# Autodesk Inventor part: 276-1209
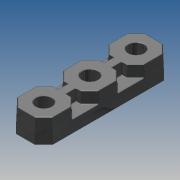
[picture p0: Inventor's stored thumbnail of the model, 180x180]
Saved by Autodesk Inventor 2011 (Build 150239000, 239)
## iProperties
Company: Autodesk Inc.
Created: 2010-06
Part Number: 276-1209
Document SubType Name: Modeling
Designer: Autodesk Inc.
Density: 1 g/cm^3
Catalog Web Link: http://www.vexrobotics.com/276-1209.html
Description: The Bearing Flat mounts directly on a piece of VEX structure and supports a shaft which runs perpendicular and directly through
Vendor: Innovation First, Inc.
Author: Autodesk Inc.
Title: VEX Robotics Kit of Parts
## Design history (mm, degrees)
sketch "Sketch1"
  geometry: L1 (11.392, 8.68)-(5.192, 8.68); L2 (5.192, 1.48)-(11.392, 1.48); L3 (4.802, 6.071)-(4.802, 6.833); L4 (5.192, 8.68)-(5.192, 1.48); L5 (4.63, 6.071)-(4.802, 6.071); L6 (4.802, 4.089)-(4.63, 4.089); L7 (4.802, 3.327)-(4.802, 4.089); L8 (30.483, 0)-(0, 0); L9 (0, 10.16)-(30.483, 10.16); L10 (0.281, 6.833)-(0.281, 6.071); L11 (0.281, 6.071)-(0.453, 6.071); L12 (0.453, 4.089)-(0.281, 4.089); L13 (1.551, 2.819)-(1.551, 2.992); L14 (0.281, 4.089)-(0.281, 3.327); L15 (0.789, 2.819)-(1.551, 2.819); L16 (-2.538, 2.538)-(0, 0); L17 (-2.538, 2.538)-(-2.538, 7.622); L18 (1.551, 7.168)-(1.551, 7.341); L19 (1.551, 7.341)-(0.789, 7.341); L20 (3.532, 2.992)-(3.532, 2.819); L21 (3.532, 7.341)-(3.532, 7.168); L22 (3.532, 2.819)-(4.294, 2.819); L23 (4.294, 7.341)-(3.532, 7.341); L24 (28.932, 2.992)-(28.932, 2.819); L25 (28.932, 2.819)-(29.694, 2.819); L26 (30.202, 4.089)-(30.03, 4.089); L27 (30.202, 3.327)-(30.202, 4.089); L28 (33.022, 2.538)-(30.483, 0); L29 (28.932, 7.341)-(28.932, 7.168); L30 (30.03, 6.071)-(30.202, 6.071); L31 (30.202, 6.071)-(30.202, 6.833); L32 (29.694, 7.341)-(28.932, 7.341); L33 (33.022, 7.622)-(33.022, 2.538); L34 (33.022, 7.622)-(30.483, 10.16); L35 (26.951, 2.819)-(26.951, 2.992); L36 (26.951, 7.168)-(26.951, 7.341); L37 (26.951, 7.341)-(26.189, 7.341); L38 (25.681, 6.833)-(25.681, 6.071); L39 (25.681, 6.071)-(25.853, 6.071); L40 (25.853, 4.089)-(25.681, 4.089); L41 (26.189, 2.819)-(26.951, 2.819); L42 (25.681, 4.089)-(25.681, 3.327); L43 (12.981, 6.833)-(12.981, 6.071); L44 (14.251, 7.341)-(13.489, 7.341); L45 (14.251, 7.168)-(14.251, 7.341); L46 (12.981, 6.071)-(13.153, 6.071); L47 (13.489, 2.819)-(14.251, 2.819); L48 (12.981, 4.089)-(12.981, 3.327); L49 (13.153, 4.089)-(12.981, 4.089); L50 (14.251, 2.819)-(14.251, 2.992); L51 (17.502, 3.327)-(17.502, 4.089); L52 (16.232, 2.819)-(16.994, 2.819); L53 (16.232, 2.992)-(16.232, 2.819); L54 (17.502, 4.089)-(17.33, 4.089); L55 (16.994, 7.341)-(16.232, 7.341); L56 (17.502, 6.071)-(17.502, 6.833); L57 (17.33, 6.071)-(17.502, 6.071); L58 (16.232, 7.341)-(16.232, 7.168); L59 (11.392, 1.48)-(11.392, 8.68); L60 (19.092, 1.48)-(25.292, 1.48); L61 (25.292, 8.68)-(19.092, 8.68); L62 (19.092, 8.68)-(19.092, 1.48); L63 (25.292, 1.48)-(25.292, 8.68); L64 (-2.538, 7.622)-(0, 10.16); C1 r 2.121 at (2.542, 5.08); C2 r 2.121 at (27.942, 5.08); C3 r 2.121 at (15.242, 5.08); A1 r 2.311 centre (2.542, 5.08) between (0.453, 4.089) and (1.551, 2.992); A2 r 2.311 centre (2.542, 5.08) between (1.551, 7.168) and (0.453, 6.071); A3 r 2.311 centre (2.542, 5.08) between (3.532, 2.992) and (4.63, 4.089); A4 r 2.311 centre (2.542, 5.08) between (4.63, 6.071) and (3.532, 7.168); A5 r 2.311 centre (27.942, 5.08) between (28.932, 2.992) and (30.03, 4.089); A6 r 2.311 centre (27.942, 5.08) between (30.03, 6.071) and (28.932, 7.168); A7 r 2.311 centre (27.942, 5.08) between (26.951, 7.168) and (25.853, 6.071); A8 r 2.311 centre (27.942, 5.08) between (25.853, 4.089) and (26.951, 2.992); A9 r 2.311 centre (15.242, 5.08) between (14.251, 7.168) and (13.153, 6.071); A10 r 2.311 centre (15.242, 5.08) between (13.153, 4.089) and (14.251, 2.992); A11 r 2.311 centre (15.242, 5.08) between (16.232, 2.992) and (17.33, 4.089); A12 r 2.311 centre (15.242, 5.08) between (17.33, 6.071) and (16.232, 7.168); 1 further point
  constraints: 128 end point, 24 point on circle, 15 centre point, 36 other
extrude "Extrusion1" new body sketch "Sketch1" distance "d0" = 6.35; taper "d1" = -2 deg
sketch "Sketch3"
  geometry: L1 (-0.092, 0.222)-(-30.391, 0.222) reference; L2 (2.317, 2.63)-(-0.092, 0.222) reference; L3 (2.317, 7.53)-(2.317, 2.63) reference; L4 (-0.092, 9.938)-(2.317, 7.53) reference; L5 (-32.8, 7.53)-(-30.391, 9.938) reference; L6 (-32.8, 2.63)-(-32.8, 7.53) reference; L7 (-30.391, 0.222)-(-32.8, 2.63) reference; L8 (-22.861, 3.956)-(-20.211, 3.956); L9 (-20.211, 2.636)-(-20.211, 3.956); L10 (-20.211, 2.636)-(-17.67, 0.095); L11 (-22.861, 3.956)-(-22.861, 2.571); L12 (-25.337, 0.095)-(-22.861, 2.571); L13 (-0.092, 0.222)-(-30.391, 0.222); L14 (0.013, -0.032)-(2.571, 2.525); L15 (2.571, 2.525)-(2.571, 7.635); L16 (2.571, 7.635)-(0.013, 10.192); L17 (-30.496, 10.192)-(-33.054, 7.635); L18 (-33.054, 7.635)-(-33.054, 2.525); L19 (-33.054, 2.525)-(-30.496, -0.032); L20 (-17.67, 0.095)-(-25.337, 0.095); C1 r 2.121 at (-15.242, 5.08); C2 r 2.121 at (-2.542, 5.08); C3 r 2.121 at (-27.942, 5.08); 2 further points
  constraints: 26 end point, 3 centre point, 1 parallel, 4 other
  dimensions: "d6" = 0.127 distance between parallel lines of L20 L1
extrude "Extrusion2" cut sketch "Sketch3" distance "d4" = 3.175; taper "d5" = 0 deg
workplane "Work Plane3"
mirror "Mirror1"
workplane "Work Plane4"
mirror "Mirror2"
hole "Hole1" sketch "Sketch1" diameter "d7" = 4.2418; stored, may be unused: countersink angle "d11" = 82 deg, drill point angle "d13" = 118 deg; dims "d8" = 19.05, "d9" = 9.525, "d10" = 6.35, "d12" = 25.4
extrude "Extrusion3" join sketch "Sketch1" distance "d14" = 0.6858; taper "d15" = -2 deg
extrude "Extrusion4" cut sketch "Sketch1" distance "d16" = 2.032; taper "d17" = -2 deg
fillet "Fillet1" dims "d18" = 0.254
fillet "Fillet2" dims "d19" = 0.254
fillet "Fillet3" dims "d20" = 0.254
fillet "Fillet4" dims "d21" = 0.254
fillet "Fillet5" dims "d22" = 0.254
fillet "Fillet6" dims "d23" = 0.254
fillet "Fillet7" dims "d24" = 0.254
fillet "Fillet8" dims "d25" = 0.254
chamfer "Chamfer1" distance "d26" = 0.127; stored, may be unused: second distance "d27" = 3.175, angle "d28" = 45 deg
body "Solid1"
